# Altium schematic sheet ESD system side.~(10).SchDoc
size A3; SheetNumber: 14; SheetTotal: 15
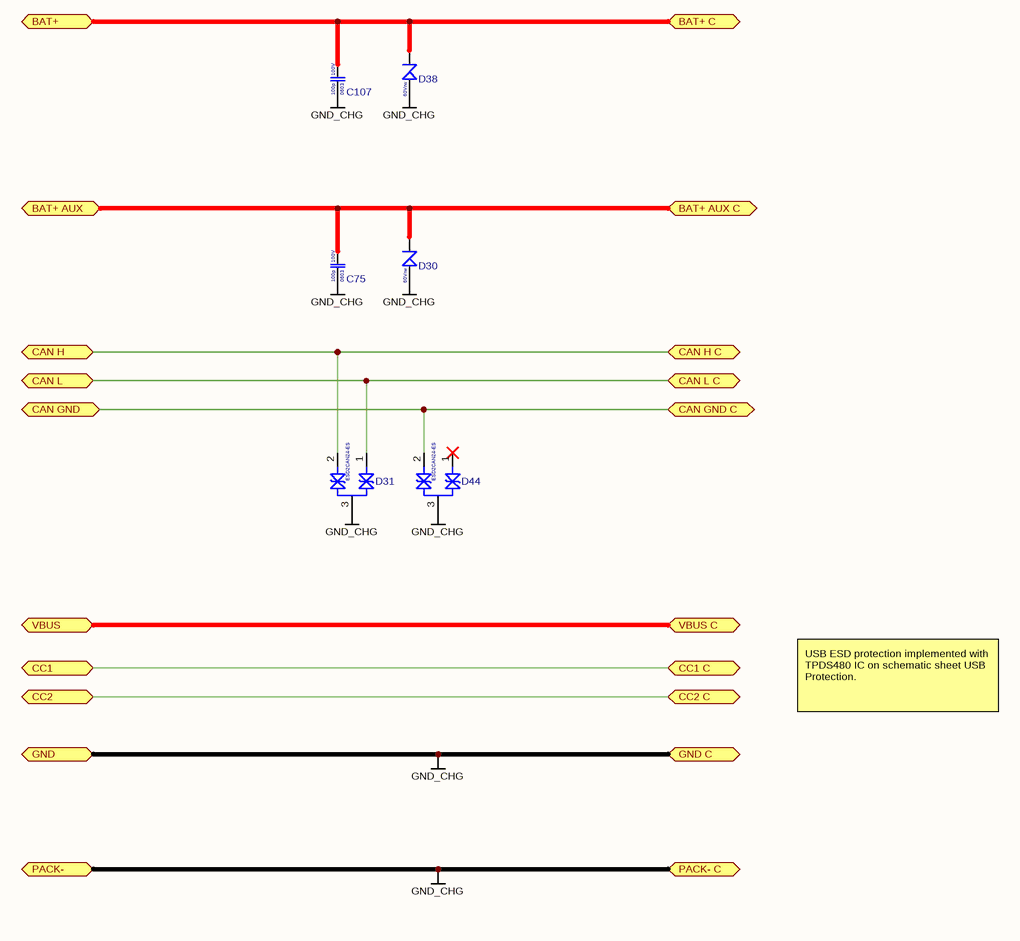
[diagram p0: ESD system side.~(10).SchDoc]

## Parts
C75  Voltage Rating: 100V  Case Code (Imperial): 0603  Capacitance: 100p  [CAP 0603]  (hidden comment: CC0603JRNPO0BN101)
C107  Voltage Rating: 100V  Case Code (Imperial): 0603  Capacitance: 100p  [CAP 0603]  (hidden comment: CC0603JRNPO0BN101)
D30  Reverse Voltage: 60Vrw  [DO-214AA]  (hidden comment: SMBJ60A)
D31  ESD2CAN24-ES  [SOT-23 123]
D38  Reverse Voltage: 60Vrw  [DO-214AA]  (hidden comment: SMBJ60A)
D44  ESD2CAN24-ES  [SOT-23 123]

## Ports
BAT+ (bidir, see Arhitecture[6A]), BAT+ AUX (bidir, see Arhitecture[6A]), BAT+ AUX C (bidir, see Arhitecture[7A]), BAT+ C (bidir, see Arhitecture[7A]), CAN GND (bidir, see Arhitecture[6B], BMS[8B], MCU[8B]), CAN GND C (bidir, see Arhitecture[7B]), CAN H (bidir, see Arhitecture[6B], BMS[8B], MCU[8A]), CAN H C (bidir, see Arhitecture[7B]), CAN L (bidir, see Arhitecture[6B], BMS[8B], MCU[8B]), CAN L C (bidir, see Arhitecture[7B]), CC1 (bidir, see Arhitecture[6B], CHARGER[8B]), CC1 C (bidir, see Arhitecture[7B]), CC2 (bidir, see Arhitecture[6C], CHARGER[8B]), CC2 C (bidir, see Arhitecture[7C]), GND (bidir, see Arhitecture[6C], CHARGER[8C]), GND C (bidir, see Arhitecture[7C]), PACK- (bidir, see Arhitecture[6D], BMS[8D], CHARGER[1C]), PACK- C (bidir, see Arhitecture[7D]), VBUS (bidir, see Arhitecture[6B], CHARGER[8A], Power path switch[5B], USB protection[5A]), VBUS C (bidir, see Arhitecture[7B])

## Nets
GND_CHG: C75.1 C107.1 D30.A D31.3 D38.A D44.3 ; port GND C, port GND, port PACK- C, port PACK-
BAT+: C107.2 D38.K ; port BAT+ C, port BAT+
BAT+ AUX: C75.2 D30.K ; port BAT+ AUX, port BAT+ AUX C
CAN GND: D44.2 ; port CAN GND, port CAN GND C
CAN H: D31.2 ; port CAN H, port CAN H C
CAN L: D31.1 ; port CAN L, port CAN L C
CC1: port CC1 C, port CC1
CC2: port CC2 C, port CC2
VBUS: port VBUS C, port VBUS

Not connected (* = marked no-connect by the designer): D44 1*

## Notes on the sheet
- USB ESD protection implemented with TPDS480 IC on schematic sheet USB Protection.

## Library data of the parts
C75 C107 = CC0603JRNPO0BN101: Cap 100pF 100V 0603 NP0; Manufacturer: Yageo; Manufacturer Part Number: CC0603KRX7R9BB104
D30 D38 = SMBJ60A: TVS ESD Zener UniD 60Vrw 1uA; Manufacturer: Shandong Jingdao Microelectronics
D31 D44 = ESD2CAN24-ES: ESD TVS CAN; Manufacturer: ElecSuper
